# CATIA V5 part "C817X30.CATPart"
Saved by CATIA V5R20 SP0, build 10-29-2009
Part number: C817X30
Source: Unknown
Property "A": "101.0"
Property "ARTICLENO": "C817XC30"
Property "B": "22"
Property "BOMINFO": "C817XC30"
Property "C": "27.0"
Property "CA": "C817XC30"
Property "D": "62"
Property "DES": "EYEBOLT TWISTER WITH BEARING M30 WITH KEY"
Property "E": "80"
Property "F": "53.0"
Property "K": "106"
Property "L": "44.0"
Property "LINA": "C817XC30"
Property "NB": "C817XC30"
Property "NBSYN": "$CODE."
Property "NN": "C817X"
Property "NT": "Eyebolt twister with bearing"
Property "SIZE": "M30"
Property "SUPPLIER": "CF"
Property "WEIGHT": "4000"
Property "WLL": "4.50"
Bounding box of the stored display mesh (mm): x -52.999 to 52.999, y -44 to 123, z -42.712 to 42.712
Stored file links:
  C:\Users\Utente\Desktop\3D files 817X\C817X30.CATPart
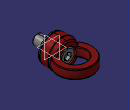
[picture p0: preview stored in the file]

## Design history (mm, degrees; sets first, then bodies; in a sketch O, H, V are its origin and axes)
Body1 "Geometry.1" (main body)
  Solid1 "C817XC30.catpart": solid without history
